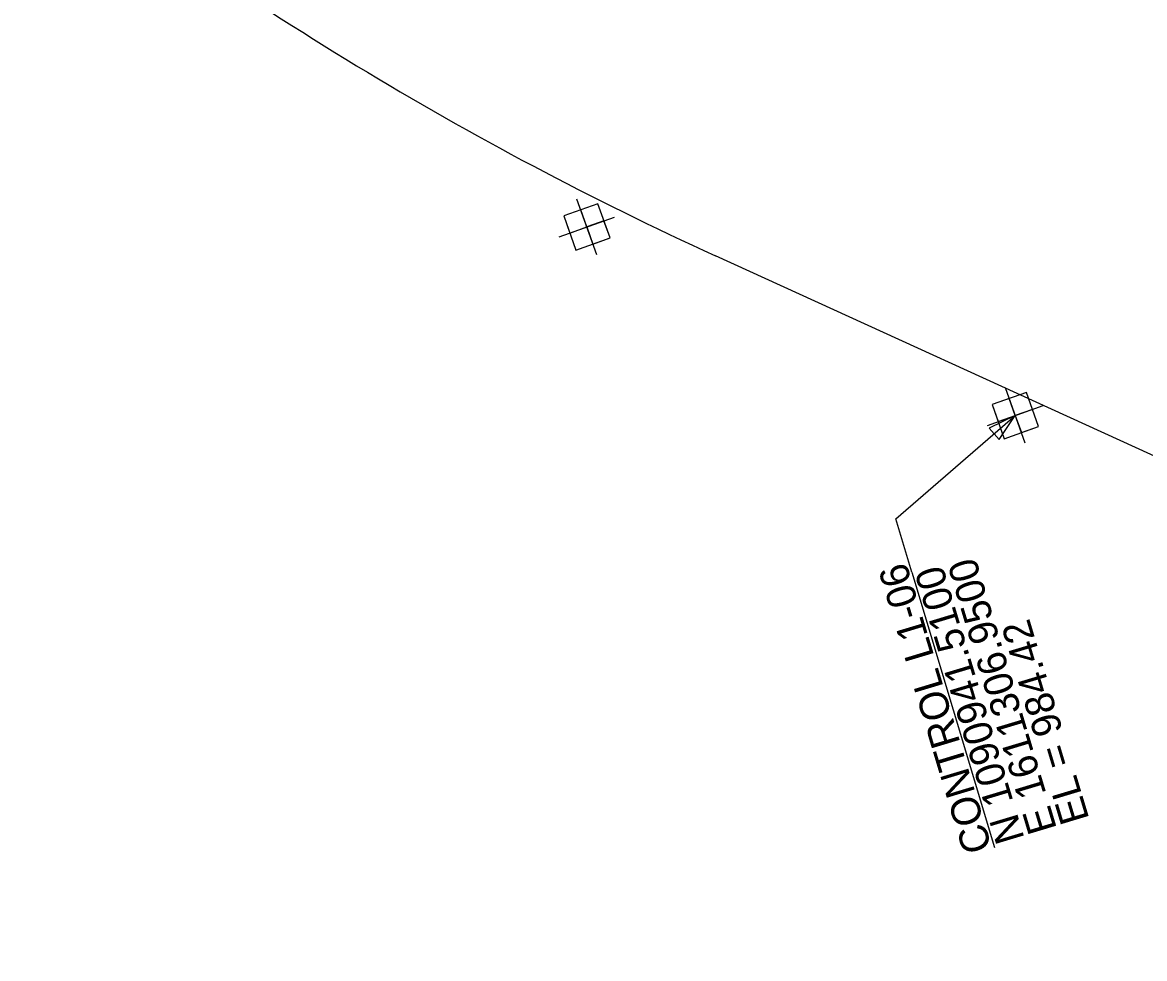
# Model space of a CAD drawing. Extents: x 1603447 to 1622636, y 1083818 to 1103958.
# Drawn here: x 1609664 to 1611521, y 1090044 to 1091591 of the extents above; entities that cross this region are included whole.
import ezdxf

# ---------------------------------------------------------------- set-up
doc = ezdxf.new("R2010")
doc.units = 0
for name, color, linetype in [('RD_HC_Points', 7, 'Continuous'), ('RD_HC_SUR_CL400', 7, 'Continuous'), ('RD_SHT_Misc1', 7, 'Continuous')]:
    doc.layers.add(name, color=color, linetype=linetype)

msp = doc.modelspace()

# ---------------------------------------------------------------- linework, layer by layer
at = {"layer": 'RD_HC_Points'}
msp.add_line((1611135.6, 1090682.3), (1611272.6, 1090227.1), dxfattribs=at)
msp.add_lwpolyline([(1611135.6, 1090682.3), (1611109, 1090770.7), (1611306.9, 1090941.5)], dxfattribs=at)
msp.add_lwpolyline([(1611280, 1090901.8), (1611306.9, 1090941.5), (1611263.7, 1090920.6)], close=True, dxfattribs=at)
at = {"layer": 'RD_HC_SUR_CL400'}
msp.add_line((1613356.7, 1090043.6), (1610810.9, 1091205.6), dxfattribs=at)
msp.add_arc((1613190, 1096417.9), 5729.6, 232.02562, 245.46665, dxfattribs=at)
at = {"layer": 'RD_SHT_Misc1'}
for p, q in [((1610614.5, 1091207.4), (1610581.8, 1091299.2)), ((1610598.1, 1091253.3), (1610588.1, 1091281.6)), ((1610552.2, 1091237), (1610644.1, 1091269.6)), ((1610626.4, 1091263.3), (1610598.1, 1091253.3)), ((1610569.9, 1091243.2), (1610598.1, 1091253.3)), ((1610598.1, 1091253.3), (1610608.2, 1091225)), ((1611323.3, 1090895.6), (1611290.6, 1090987.4)), ((1611306.9, 1090941.5), (1611296.9, 1090969.8)), ((1611261, 1090925.2), (1611352.9, 1090957.8)), ((1611278.7, 1090931.5), (1611306.9, 1090941.5)), ((1611335.2, 1090951.6), (1611306.9, 1090941.5)), ((1611306.9, 1090941.5), (1611317, 1090913.2))]:
    msp.add_line(p, q, dxfattribs=at)
for points in [[(1610636.5, 1091235.1), (1610616.4, 1091291.6), (1610559.8, 1091271.5), (1610579.9, 1091215)], [(1611345.3, 1090923.3), (1611325.2, 1090979.8), (1611268.6, 1090959.7), (1611288.7, 1090903.2)]]:
    msp.add_lwpolyline(points, close=True, dxfattribs=at)
for points in [[(1610588.1, 1091281.6), (1610559.8, 1091271.5), (1610569.9, 1091243.2)], [(1610636.5, 1091235.1), (1610626.4, 1091263.3)], [(1610608.2, 1091225), (1610636.5, 1091235.1)], [(1611296.9, 1090969.8), (1611268.6, 1090959.7), (1611278.7, 1090931.5)], [(1611345.3, 1090923.3), (1611335.2, 1090951.6)], [(1611317, 1090913.2), (1611345.3, 1090923.3)]]:
    msp.add_lwpolyline(points, dxfattribs=at)

# ---------------------------------------------------------------- texts
at = {"layer": 'RD_HC_Points'}
for s, p in [('E 1611306.9500', (1611376, 1090258.2)), ('CONTROL L1-06', (1611268.7, 1090226)), ('N 1090941.5100', (1611322.4, 1090242.1)), ('EL = 984.42', (1611429.6, 1090274.4))]:
    msp.add_text(s, height=48, rotation=106.7478, dxfattribs=at).set_placement(p)

doc.saveas('drawing.dxf')
